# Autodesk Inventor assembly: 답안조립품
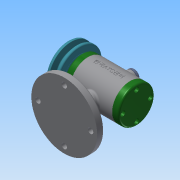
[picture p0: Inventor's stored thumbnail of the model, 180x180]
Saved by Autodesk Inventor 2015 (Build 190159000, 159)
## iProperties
Created: 2018-12
Part Number: 답안조립품
Document SubType Name: Assembly
Designer: 405-15
Author: 405-15
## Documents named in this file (14)
- C:\Users\405-15\Desktop\481207V1052\답안조립품.iam
- C:\Users\405-15\Desktop\481207V1052\본체.ipt
- C:\Users\405-15\Desktop\481207V1052\축.ipt
- C:\Users\405-15\Desktop\481207V1052\키 3 x 3 x 12.ipt
- C:\Users\405-15\Desktop\481207V1052\베어링 15 x 32 x 9.ipt
- C:\Users\405-15\Desktop\481207V1052\뒤커버.ipt
- C:\Users\405-15\Desktop\481207V1052\앞커버.ipt
- C:\Users\405-15\Desktop\481207V1052\오일 실 15 25 7.ipt
- C:\Users\405-15\Desktop\481207V1052\V벨트풀리.ipt
- C:\Users\405-15\Desktop\481207V1052\스프링와셔 8.ipt
- C:\Users\405-15\Desktop\481207V1052\와셔 8x17.ipt
- C:\Users\405-15\Desktop\481207V1052\너트 M8.ipt
- 너트 M8.ipt
- C:\Users\405-15\Desktop\481207V1052\고무캡.ipt
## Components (2 placed, 2 different names)
1. V벨트풀리:1
2. 고무캡:1 — 각도:2
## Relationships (1: Angle 1)
- 각도:2 [Angle]: 고무캡:1
